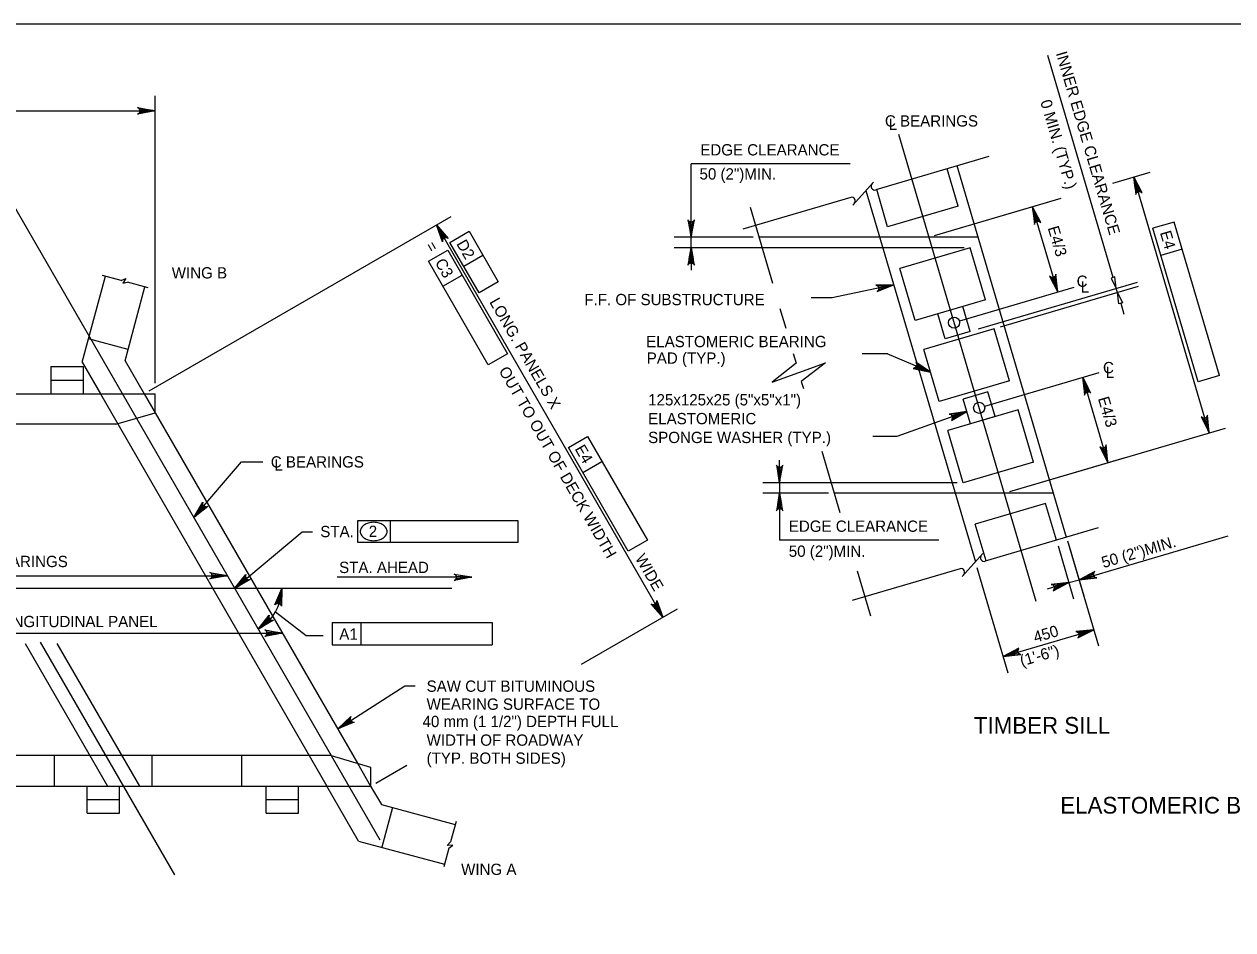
# Model space of a CAD drawing. Extents: x -8 to 75, y -110 to 0.
# Drawn here: x 46.85 to 59.7, y -54.37 to -44.75 of the extents above; entities that cross this region are included whole.
import ezdxf

# ---------------------------------------------------------------- set-up
doc = ezdxf.new("R2010")
doc.units = 0
for name, color, linetype in [('1', 7, 'Continuous'), ('2', 7, 'Continuous'), ('3', 7, 'Continuous'), ('4', 7, 'Continuous'), ('7', 7, 'Continuous')]:
    doc.layers.add(name, color=color, linetype=linetype)

msp = doc.modelspace()

# ---------------------------------------------------------------- linework, layer by layer
at = {"layer": '1'}
msp.add_lwpolyline([(35.75, -65.25), (67.25, -65.25), (67.25, -44.75), (35.75, -44.75)], close=True, dxfattribs=at)
at = {"layer": '2'}
for p, q in [((47.471, -48.343), (47.717, -47.428)), ((47.96, -48.208), (48.138, -47.541)), ((47.96, -48.208), (47.538, -48.095)), ((47.928, -48.326), (47.96, -48.208)), ((47.136, -48.388), (47.136, -48.677)), ((47.136, -48.388), (47.482, -48.388)), ((47.471, -48.343), (47.664, -48.677)), ((47.482, -48.388), (47.482, -48.677)), ((47.928, -48.326), (48.13, -48.677)), ((40.486, -48.677), (48.247, -48.677)), ((47.664, -48.677), (50.071, -52.846)), ((48.13, -48.677), (48.247, -48.879)), ((48.247, -48.879), (48.247, -48.677)), ((47.828, -49.001), (48.247, -48.879)), ((48.247, -48.879), (50.397, -52.603)), ((47.828, -49.001), (40.906, -49.001)), ((50.118, -52.521), (43.196, -52.521)), ((50.118, -52.521), (50.537, -52.644)), ((50.397, -52.603), (50.537, -52.846)), ((50.537, -52.644), (50.537, -52.846)), ((42.777, -52.846), (50.537, -52.846)), ((47.523, -53.134), (47.523, -52.846)), ((47.869, -53.134), (47.869, -52.846)), ((49.426, -53.134), (49.426, -52.846)), ((49.772, -53.134), (49.772, -52.846)), ((50.408, -53.43), (50.071, -52.846)), ((50.537, -52.846), (50.651, -53.043)), ((50.651, -53.043), (50.769, -53.075)), ((47.523, -53.134), (47.869, -53.134)), ((49.426, -53.134), (49.772, -53.134)), ((50.769, -53.075), (50.656, -53.496)), ((50.769, -53.075), (51.436, -53.253)), ((50.408, -53.43), (51.323, -53.675))]:
    msp.add_line(p, q, dxfattribs=at)
at = {"layer": '3'}
for p, q in [((57.109, -46.157), (55.908, -46.511)), ((57.934, -50.203), (56.772, -46.256)), ((58.425, -46.439), (58.823, -46.322)), ((59.451, -49.092), (58.651, -46.373)), ((55.881, -46.428), (55.664, -46.674)), ((55.64, -46.59), (54.493, -46.928)), ((55.802, -46.517), (56.965, -50.463)), ((56.532, -46.997), (57.877, -46.6)), ((54.571, -46.696), (54.808, -47.502)), ((56.781, -46.684), (56.033, -46.904)), ((56.995, -47.014), (54.664, -47.014)), ((56.911, -47.125), (56.163, -47.345)), ((47.887, -47.474), (47.687, -47.42)), ((47.887, -47.474), (47.934, -47.453)), ((47.934, -47.453), (47.902, -47.502)), ((47.902, -47.502), (47.952, -47.491)), ((48.171, -47.55), (47.952, -47.491)), ((57, -47.987), (58.688, -47.49)), ((57.233, -47.967), (58.701, -47.534)), ((54.887, -47.77), (54.949, -47.98)), ((57.074, -47.678), (56.326, -47.899)), ((56.832, -47.75), (56.568, -47.828)), ((57.165, -47.987), (56.417, -48.207)), ((56.91, -48.014), (56.646, -48.092)), ((55.028, -48.248), (55.059, -48.353)), ((47.136, -48.533), (47.482, -48.533)), ((55.115, -48.545), (55.138, -48.622)), ((57.328, -48.541), (56.58, -48.761)), ((57.099, -48.656), (56.835, -48.734)), ((57.419, -48.849), (56.671, -49.069)), ((57.177, -48.92), (56.913, -48.998)), ((57.333, -49.716), (59.624, -49.041)), ((55.333, -49.286), (55.526, -49.938)), ((57.582, -49.403), (56.834, -49.623)), ((57.796, -49.733), (55.465, -49.733)), ((57.712, -49.844), (56.964, -50.064)), ((58.271, -50.103), (57.071, -50.457)), ((57.043, -50.374), (56.826, -50.62)), ((56.802, -50.536), (55.655, -50.874)), ((55.708, -50.557), (55.849, -51.036)), ((46.864, -51.329), (47.74, -52.846)), ((47.203, -51.329), (48.079, -52.846)), ((47.176, -52.846), (47.176, -52.521)), ((48.215, -52.846), (48.215, -52.521)), ((49.167, -52.846), (49.167, -52.521)), ((47.523, -52.99), (47.869, -52.99)), ((49.426, -52.99), (49.772, -52.99)), ((51.445, -53.221), (51.386, -53.439)), ((51.352, -53.477), (51.386, -53.439)), ((51.369, -53.505), (51.315, -53.705)), ((51.41, -53.474), (51.352, -53.477)), ((51.369, -53.505), (51.41, -53.474))]:
    msp.add_line(p, q, dxfattribs=at)
for points in [[(58.704, -46.482), (58.665, -46.493), (58.651, -46.373)], [(59.437, -48.971), (59.398, -48.982), (59.451, -49.092)]]:
    msp.add_lwpolyline(points, close=True, dxfattribs=at)
for centre, start, end in [((55.897, -46.472), 136.412, 286.412), ((55.648, -46.63), 318.5448, 101.0834), ((57.059, -50.418), 136.412, 286.412), ((56.81, -50.576), 318.5448, 101.0834)]:
    msp.add_arc(centre, 0.0409, start, end, dxfattribs=at)
at = {"layer": '4'}
for p, q in [((58.429, -47.441), (57.734, -45.082)), ((48.247, -48.566), (48.247, -45.513)), ((40.486, -45.671), (48.247, -45.671)), ((57.612, -50.886), (56.15, -45.922)), ((53.944, -46.894), (53.944, -46.233)), ((55.635, -46.233), (53.944, -46.233)), ((50.637, -53.422), (46.69, -46.585)), ((56.532, -46.997), (57.747, -46.639)), ((57.841, -47.596), (57.574, -46.69)), ((48.184, -48.645), (51.393, -46.793)), ((51.237, -46.883), (53.644, -51.052)), ((59.079, -46.852), (58.853, -46.919)), ((59.56, -48.483), (59.079, -46.852)), ((51.38, -47.07), (51.584, -46.951)), ((51.584, -46.951), (51.894, -47.488)), ((54.602, -47.014), (53.764, -47.014)), ((53.944, -47.125), (53.944, -47.014)), ((59.333, -48.55), (58.853, -46.919)), ((51.153, -47.269), (51.357, -47.151)), ((51.357, -47.151), (51.993, -48.251)), ((51.69, -47.606), (51.38, -47.07)), ((56.848, -47.125), (53.764, -47.125)), ((59.165, -47.142), (58.938, -47.209)), ((51.788, -48.37), (51.153, -47.269)), ((51.526, -47.322), (51.73, -47.204)), ((53.944, -47.245), (53.944, -47.365)), ((51.306, -47.534), (51.51, -47.416)), ((51.894, -47.488), (51.69, -47.606)), ((55.442, -47.657), (55.221, -47.657)), ((56.799, -47.903), (58.014, -47.545)), ((58.476, -47.601), (58.463, -47.557)), ((58.51, -47.716), (58.544, -47.831)), ((51.993, -48.251), (51.788, -48.37)), ((56.035, -48.253), (55.761, -48.253)), ((57.066, -48.809), (58.281, -48.452)), ((58.375, -49.409), (58.108, -48.502)), ((59.56, -48.483), (59.333, -48.55)), ((52.639, -49.249), (52.843, -49.131)), ((52.843, -49.131), (53.479, -50.232)), ((56.13, -49.131), (55.875, -49.131)), ((53.274, -50.35), (52.639, -49.249)), ((48.657, -49.992), (49.166, -49.402)), ((49.166, -49.402), (49.391, -49.402)), ((52.791, -49.514), (52.996, -49.396)), ((54.885, -49.503), (54.885, -49.383)), ((57.333, -49.716), (58.548, -49.358)), ((56.772, -49.623), (54.705, -49.623)), ((54.885, -49.623), (54.885, -49.733)), ((55.403, -49.733), (54.705, -49.733)), ((54.885, -49.853), (54.885, -50.232)), ((50.4, -50.258), (50.4, -50.022)), ((50.4, -50.022), (52.101, -50.022)), ((50.75, -50.258), (50.75, -50.022)), ((52.101, -50.022), (52.101, -50.258)), ((49.091, -50.745), (49.809, -50.145)), ((49.809, -50.145), (49.919, -50.145)), ((53.479, -50.232), (53.274, -50.35)), ((56.576, -50.232), (54.885, -50.232)), ((58.067, -50.653), (59.654, -50.185)), ((52.101, -50.258), (50.4, -50.258)), ((57.844, -50.294), (58.01, -50.857)), ((57.945, -50.239), (58.274, -51.357)), ((57.952, -50.262), (58.118, -50.825)), ((41.836, -50.61), (49.014, -50.61)), ((56.982, -50.523), (57.311, -51.641)), ((51.399, -50.745), (39.31, -50.745)), ((51.613, -50.627), (50.18, -50.627)), ((57.959, -50.684), (57.729, -50.752)), ((57.959, -50.684), (58.067, -50.653)), ((49.525, -50.995), (49.852, -51.244)), ((52.779, -51.552), (53.8, -50.962)), ((50.129, -51.109), (51.83, -51.109)), ((50.129, -51.109), (50.129, -51.345)), ((50.432, -51.109), (50.432, -51.345)), ((51.83, -51.109), (51.83, -51.345)), ((41.956, -51.222), (49.6, -51.222)), ((49.852, -51.244), (50.031, -51.244)), ((57.261, -51.468), (58.224, -51.184)), ((47.025, -51.315), (48.453, -53.787)), ((50.129, -51.345), (51.83, -51.345)), ((50.187, -52.239), (50.9, -51.781)), ((50.9, -51.781), (51.01, -51.781)), ((50.591, -52.814), (50.921, -52.624))]:
    msp.add_line(p, q, dxfattribs=at)
for points in [[(48.247, -45.671), (48.06, -45.706), (48.075, -45.696), (48.082, -45.683), (48.084, -45.671), (48.082, -45.658), (48.075, -45.646), (48.06, -45.636), (48.247, -45.671), (48.075, -45.646), (48.082, -45.658), (48.247, -45.671), (48.084, -45.671), (48.082, -45.683), (48.247, -45.671), (48.075, -45.696)], [(58.651, -46.373), (58.67, -46.561), (58.675, -46.545), (58.685, -46.534), (58.696, -46.529), (58.709, -46.527), (58.723, -46.531), (58.737, -46.542), (58.651, -46.373), (58.723, -46.531), (58.709, -46.527), (58.651, -46.373), (58.696, -46.529), (58.685, -46.534), (58.651, -46.373), (58.675, -46.545)], [(57.574, -46.69), (57.593, -46.878), (57.599, -46.862), (57.609, -46.851), (57.62, -46.846), (57.633, -46.844), (57.647, -46.848), (57.66, -46.859), (57.574, -46.69), (57.647, -46.848), (57.633, -46.844), (57.574, -46.69), (57.62, -46.846), (57.609, -46.851), (57.574, -46.69), (57.599, -46.862)], [(51.237, -46.883), (51.361, -47.027), (51.345, -47.02), (51.33, -47.02), (51.318, -47.024), (51.308, -47.032), (51.301, -47.045), (51.3, -47.062), (51.237, -46.883), (51.301, -47.045), (51.308, -47.032), (51.237, -46.883), (51.318, -47.024), (51.33, -47.02), (51.237, -46.883), (51.345, -47.02)], [(53.944, -47.014), (53.979, -46.828), (53.969, -46.842), (53.957, -46.85), (53.944, -46.852), (53.932, -46.85), (53.919, -46.842), (53.909, -46.828), (53.944, -47.014), (53.919, -46.842), (53.932, -46.85), (53.944, -47.014), (53.944, -46.852), (53.957, -46.85), (53.944, -47.014), (53.969, -46.842)], [(53.944, -47.125), (53.909, -47.311), (53.919, -47.297), (53.932, -47.289), (53.944, -47.287), (53.957, -47.289), (53.969, -47.297), (53.979, -47.311), (53.944, -47.125), (53.969, -47.297), (53.957, -47.289), (53.944, -47.125), (53.944, -47.287), (53.932, -47.289), (53.944, -47.125), (53.919, -47.297)], [(57.841, -47.596), (57.822, -47.407), (57.816, -47.424), (57.807, -47.435), (57.795, -47.44), (57.783, -47.442), (57.769, -47.438), (57.755, -47.427), (57.841, -47.596), (57.769, -47.438), (57.783, -47.442), (57.841, -47.596), (57.795, -47.44), (57.807, -47.435), (57.841, -47.596), (57.816, -47.424)], [(56.097, -47.519), (55.442, -47.657)], [(56.097, -47.519), (55.908, -47.523), (55.924, -47.53), (55.934, -47.541), (55.938, -47.552), (55.939, -47.565), (55.934, -47.579), (55.922, -47.592), (56.097, -47.519), (55.934, -47.579), (55.939, -47.565), (56.097, -47.519), (55.938, -47.552), (55.934, -47.541), (56.097, -47.519), (55.924, -47.53)], [(56.488, -48.449), (56.028, -48.251)], [(55.059, -48.353), (54.805, -48.554), (55.371, -48.35), (55.115, -48.545)], [(56.488, -48.449), (56.331, -48.343), (56.34, -48.358), (56.342, -48.372), (56.339, -48.385), (56.332, -48.395), (56.32, -48.404), (56.303, -48.407), (56.488, -48.449), (56.32, -48.404), (56.332, -48.395), (56.488, -48.449), (56.339, -48.385), (56.342, -48.372), (56.488, -48.449), (56.34, -48.358)], [(58.108, -48.502), (58.127, -48.691), (58.133, -48.675), (58.143, -48.664), (58.154, -48.658), (58.167, -48.657), (58.181, -48.66), (58.194, -48.671), (58.108, -48.502), (58.181, -48.66), (58.167, -48.657), (58.108, -48.502), (58.154, -48.658), (58.143, -48.664), (58.108, -48.502), (58.133, -48.675)], [(56.873, -48.864), (56.13, -49.131)], [(56.873, -48.864), (56.686, -48.894), (56.703, -48.899), (56.714, -48.908), (56.72, -48.919), (56.722, -48.931), (56.72, -48.946), (56.71, -48.96), (56.873, -48.864), (56.72, -48.946), (56.722, -48.931), (56.873, -48.864), (56.72, -48.919), (56.714, -48.908), (56.873, -48.864), (56.703, -48.899)], [(59.451, -49.092), (59.432, -48.903), (59.427, -48.92), (59.417, -48.93), (59.405, -48.936), (59.393, -48.937), (59.379, -48.934), (59.365, -48.923), (59.451, -49.092), (59.379, -48.934), (59.393, -48.937), (59.451, -49.092), (59.405, -48.936), (59.417, -48.93), (59.451, -49.092), (59.427, -48.92)], [(58.375, -49.409), (58.356, -49.22), (58.35, -49.237), (58.341, -49.247), (58.329, -49.253), (58.317, -49.254), (58.302, -49.251), (58.289, -49.24), (58.375, -49.409), (58.302, -49.251), (58.317, -49.254), (58.375, -49.409), (58.329, -49.253), (58.341, -49.247), (58.375, -49.409), (58.35, -49.237)], [(54.885, -49.623), (54.92, -49.437), (54.91, -49.451), (54.898, -49.459), (54.885, -49.461), (54.873, -49.459), (54.86, -49.451), (54.85, -49.437), (54.885, -49.623), (54.86, -49.451), (54.873, -49.459), (54.885, -49.623), (54.885, -49.461), (54.898, -49.459), (54.885, -49.623), (54.91, -49.451)], [(48.657, -49.992), (48.752, -49.828), (48.75, -49.845), (48.755, -49.859), (48.763, -49.869), (48.774, -49.875), (48.788, -49.878), (48.805, -49.874), (48.657, -49.992), (48.788, -49.878), (48.774, -49.875), (48.657, -49.992), (48.763, -49.869), (48.755, -49.859), (48.657, -49.992), (48.75, -49.845)], [(54.885, -49.733), (54.85, -49.92), (54.86, -49.906), (54.873, -49.898), (54.885, -49.896), (54.898, -49.898), (54.91, -49.906), (54.92, -49.92), (54.885, -49.733), (54.91, -49.906), (54.898, -49.898), (54.885, -49.733), (54.885, -49.896), (54.873, -49.898), (54.885, -49.733), (54.86, -49.906)], [(49.014, -50.61), (48.827, -50.645), (48.841, -50.635), (48.849, -50.623), (48.851, -50.61), (48.849, -50.598), (48.841, -50.585), (48.827, -50.575), (49.014, -50.61), (48.841, -50.585), (48.849, -50.598), (49.014, -50.61), (48.851, -50.61), (48.849, -50.623), (49.014, -50.61), (48.841, -50.635)], [(49.091, -50.745), (49.212, -50.599), (49.207, -50.615), (49.21, -50.63), (49.216, -50.641), (49.226, -50.649), (49.239, -50.654), (49.257, -50.652), (49.091, -50.745), (49.239, -50.654), (49.226, -50.649), (49.091, -50.745), (49.216, -50.641), (49.21, -50.63), (49.091, -50.745), (49.207, -50.615)], [(51.613, -50.627), (51.426, -50.662), (51.441, -50.652), (51.448, -50.64), (51.45, -50.627), (51.448, -50.615), (51.441, -50.602), (51.426, -50.593), (51.613, -50.627), (51.441, -50.602), (51.448, -50.615), (51.613, -50.627), (51.45, -50.627), (51.448, -50.64), (51.613, -50.627), (51.441, -50.652)], [(58.067, -50.653), (58.256, -50.634), (58.239, -50.628), (58.228, -50.618), (58.223, -50.607), (58.221, -50.594), (58.225, -50.58), (58.236, -50.567), (58.067, -50.653), (58.225, -50.58), (58.221, -50.594), (58.067, -50.653), (58.223, -50.607), (58.228, -50.618), (58.067, -50.653), (58.239, -50.628)], [(49.592, -50.745), (49.588, -50.935), (49.581, -50.919), (49.57, -50.909), (49.558, -50.904), (49.546, -50.904), (49.532, -50.908), (49.519, -50.92), (49.592, -50.745), (49.532, -50.908), (49.546, -50.904), (49.592, -50.745), (49.558, -50.904), (49.57, -50.909), (49.592, -50.745), (49.581, -50.919)], [(57.959, -50.684), (57.771, -50.704), (57.787, -50.709), (57.798, -50.719), (57.803, -50.73), (57.805, -50.743), (57.801, -50.757), (57.791, -50.771), (57.959, -50.684), (57.801, -50.757), (57.805, -50.743), (57.959, -50.684), (57.803, -50.73), (57.798, -50.719), (57.959, -50.684), (57.787, -50.709)], [(53.644, -51.052), (53.52, -50.908), (53.536, -50.916), (53.551, -50.916), (53.563, -50.911), (53.572, -50.903), (53.58, -50.891), (53.581, -50.873), (53.644, -51.052), (53.58, -50.891), (53.572, -50.903), (53.644, -51.052), (53.563, -50.911), (53.551, -50.916), (53.644, -51.052), (53.536, -50.916)], [(49.342, -51.179), (49.46, -51.03), (49.456, -51.047), (49.458, -51.062), (49.465, -51.072), (49.474, -51.081), (49.488, -51.085), (49.506, -51.083), (49.342, -51.179), (49.488, -51.085), (49.474, -51.081), (49.342, -51.179), (49.465, -51.072), (49.458, -51.062), (49.342, -51.179), (49.456, -51.047)], [(49.6, -51.222), (49.413, -51.257), (49.428, -51.247), (49.435, -51.235), (49.437, -51.222), (49.435, -51.21), (49.428, -51.197), (49.413, -51.187), (49.6, -51.222), (49.428, -51.197), (49.435, -51.21), (49.6, -51.222), (49.437, -51.222), (49.435, -51.235), (49.6, -51.222), (49.428, -51.247)], [(58.224, -51.184), (58.035, -51.204), (58.051, -51.209), (58.062, -51.219), (58.068, -51.23), (58.069, -51.243), (58.066, -51.257), (58.055, -51.271), (58.224, -51.184), (58.066, -51.257), (58.069, -51.243), (58.224, -51.184), (58.068, -51.23), (58.062, -51.219), (58.224, -51.184), (58.051, -51.209)], [(57.261, -51.468), (57.449, -51.449), (57.433, -51.443), (57.422, -51.434), (57.416, -51.422), (57.415, -51.41), (57.419, -51.395), (57.429, -51.382), (57.261, -51.468), (57.419, -51.395), (57.415, -51.41), (57.261, -51.468), (57.416, -51.422), (57.422, -51.434), (57.261, -51.468), (57.433, -51.443)], [(50.187, -52.239), (50.325, -52.108), (50.318, -52.125), (50.319, -52.139), (50.323, -52.151), (50.332, -52.16), (50.345, -52.167), (50.362, -52.167), (50.187, -52.239), (50.345, -52.167), (50.332, -52.16), (50.187, -52.239), (50.323, -52.151), (50.319, -52.139), (50.187, -52.239), (50.318, -52.125)]]:
    msp.add_lwpolyline(points, dxfattribs=at)
for points in [[(57.627, -46.799), (57.589, -46.81), (57.574, -46.69)], [(51.314, -46.977), (51.28, -46.997), (51.237, -46.883)], [(53.964, -46.894), (53.924, -46.894), (53.944, -47.014)], [(53.964, -47.245), (53.924, -47.245), (53.944, -47.125)], [(56.097, -47.519), (55.982, -47.553), (55.978, -47.534)], [(57.826, -47.475), (57.788, -47.487), (57.841, -47.596)], [(58.448, -47.436), (58.41, -47.447), (58.463, -47.557)], [(58.529, -47.71), (58.491, -47.721), (58.476, -47.601)], [(56.488, -48.449), (56.374, -48.411), (56.382, -48.392)], [(58.161, -48.612), (58.123, -48.623), (58.108, -48.502)], [(56.873, -48.864), (56.764, -48.914), (56.757, -48.895)], [(58.36, -49.288), (58.322, -49.299), (58.375, -49.409)], [(54.905, -49.503), (54.865, -49.503), (54.885, -49.623)], [(54.905, -49.853), (54.865, -49.853), (54.885, -49.733)], [(58.176, -50.6), (58.188, -50.638), (58.067, -50.653)], [(49.164, -50.66), (49.188, -50.688), (49.091, -50.745)], [(57.839, -50.699), (57.85, -50.738), (57.959, -50.684)], [(53.601, -50.938), (53.567, -50.958), (53.644, -51.052)], [(58.103, -51.199), (58.114, -51.237), (58.224, -51.184)], [(57.37, -51.415), (57.381, -51.453), (57.261, -51.468)], [(50.305, -52.185), (50.285, -52.154), (50.201, -52.229)]]:
    msp.add_lwpolyline(points, close=True, dxfattribs=at)
for centre, radius, start, end in [((50.493, -50.141), 0.067, 148.5507, 180), ((50.53, -50.163), 0.11, 124.109, 148.5507), ((50.554, -50.198), 0.153, 105.6708, 124.109), ((50.569, -50.254), 0.211, 90, 105.6708), ((50.569, -50.254), 0.211, 74.3292, 90), ((50.585, -50.198), 0.153, 55.891, 74.3292), ((50.609, -50.163), 0.11, 31.4493, 55.891), ((50.646, -50.141), 0.067, 0, 31.4493), ((50.493, -50.141), 0.067, 180, 211.4493), ((50.53, -50.118), 0.11, 211.4493, 235.891), ((50.554, -50.083), 0.153, 235.891, 254.3292), ((50.569, -50.027), 0.211, 254.3292, 270), ((50.569, -50.027), 0.211, 270, 285.6708), ((50.585, -50.083), 0.153, 285.6708, 304.109), ((50.609, -50.118), 0.11, 304.109, 328.5507), ((50.646, -50.141), 0.067, 328.5507, 0), ((49.091, -50.745), 0.501, 299.9992, 0.0004)]:
    msp.add_arc(centre, radius, start, end, dxfattribs=at)
at = {"layer": '7'}
for p, q in [((56.781, -46.684), (56.664, -46.288)), ((56.033, -46.904), (55.917, -46.508)), ((57.074, -47.678), (56.911, -47.125)), ((56.326, -47.899), (56.163, -47.345)), ((56.91, -48.014), (56.832, -47.75)), ((56.646, -48.092), (56.568, -47.828)), ((57.328, -48.541), (57.165, -47.987)), ((56.58, -48.761), (56.417, -48.207)), ((57.177, -48.92), (57.099, -48.656)), ((56.913, -48.998), (56.835, -48.734)), ((57.582, -49.403), (57.419, -48.849)), ((56.834, -49.623), (56.671, -49.069)), ((57.827, -50.234), (57.712, -49.844)), ((57.079, -50.454), (56.964, -50.064))]:
    msp.add_line(p, q, dxfattribs=at)
for centre in [(56.739, -47.921), (57.006, -48.827)]:
    msp.add_circle(centre, 0.059, dxfattribs=at)

# ---------------------------------------------------------------- texts
at = {"layer": '3'}
for s, p in [('TIMBER SILL', (56.95, -52.289)), ('ELASTOMERIC BEARING PAD ARRANGEMENTS', (57.868, -53.138))]:
    msp.add_text(s, height=0.17717, dxfattribs=at).set_placement(p)
at = {"layer": '4'}
for s, rotation, p in [('INNER EDGE CLEARANCE', 286.412, (57.82, -45.059)), ('0 MIN. (TYP.)', 286.412, (57.654, -45.573)), ('E4/3', 286.412, (57.733, -46.914)), ('E4', 286.4738, (58.926, -46.964)), ('=', 300, (51.114, -47.102)), ('D2', 300, (51.445, -47.083)), ('C3', 300, (51.217, -47.282)), ('LONG. PANELS X', 300, (51.795, -47.701)), ('OUT TO OUT OF DECK WIDTH', 300, (51.895, -48.431)), ('E4/3', 286.412, (58.267, -48.727)), ('E4', 300, (52.703, -49.262)), ('50 (2")MIN.', 16.4163, (58.327, -50.53)), ('WIDE', 300, (53.344, -50.423)), ('A1', 359.9382, (50.204, -51.291)), ('450', 16.4163, (57.603, -51.324)), ('(1\'-6")', 16.4163, (57.459, -51.575))]:
    msp.add_text(s, height=0.12, rotation=rotation, dxfattribs=at).set_placement(p)
for s, p in [('C BEARINGS', (56.004, -45.838)), ('L', (56.045, -45.875)), ('EDGE CLEARANCE', (54.041, -46.145)), ('50 (2")MIN.', (54.033, -46.401)), ('WING B', (48.423, -47.452)), ('C', (58.042, -47.541)), ('L', (58.085, -47.602)), ('F.F. OF SUBSTRUCTURE', (52.809, -47.736)), ('ELASTOMERIC BEARING', (53.466, -48.182)), ('PAD (TYP.)', (53.472, -48.358)), ('C', (58.322, -48.459)), ('L', (58.352, -48.508)), ('125x125x25 (5"x5"x1")', (53.487, -48.801)), ('ELASTOMERIC', (53.487, -49.001)), ('SPONGE WASHER (TYP.)', (53.487, -49.201)), ('C BEARINGS', (49.476, -49.461)), ('L', (49.514, -49.495)), ('STA.', (50.002, -50.201)), ('2', (50.517, -50.199)), ('EDGE CLEARANCE', (54.982, -50.144)), ('50 (2")MIN.', (54.982, -50.41)), ('C/C BEARINGS', (46.168, -50.519)), ('STA. AHEAD', (50.202, -50.582)), ('OUT TO OUT LONGITUDINAL PANEL', (45.482, -51.157)), ('SAW CUT BITUMINOUS', (51.132, -51.844)), ('WEARING SURFACE TO', (51.132, -52.035)), ('40 mm (1 1/2") DEPTH FULL', (51.089, -52.219)), ('WIDTH OF ROADWAY', (51.132, -52.417)), ('(TYP. BOTH SIDES)', (51.132, -52.609)), ('WING A', (51.499, -53.79))]:
    msp.add_text(s, height=0.12, dxfattribs=at).set_placement(p)

doc.saveas('drawing.dxf')
